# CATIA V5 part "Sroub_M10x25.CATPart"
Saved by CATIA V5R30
Part number: Sroub_M10x25
Definition: E 1200_10x25_3
Nomenclature: E 1200_10x25_3
Source: Unknown
Description: PART--DESC
Bounding box of the stored display mesh (mm): x 147 to 163, y -98 to -82, z -219 to -184
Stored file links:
  E:\Bakalarka\Model\Forma_v7\Sroub_M10x25.CATPart
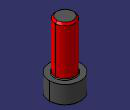
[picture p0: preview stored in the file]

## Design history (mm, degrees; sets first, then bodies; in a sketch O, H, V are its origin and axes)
Body1 "MANIFOLD_SOLID_BREP #3994" (main body)
  Solid1: solid without history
